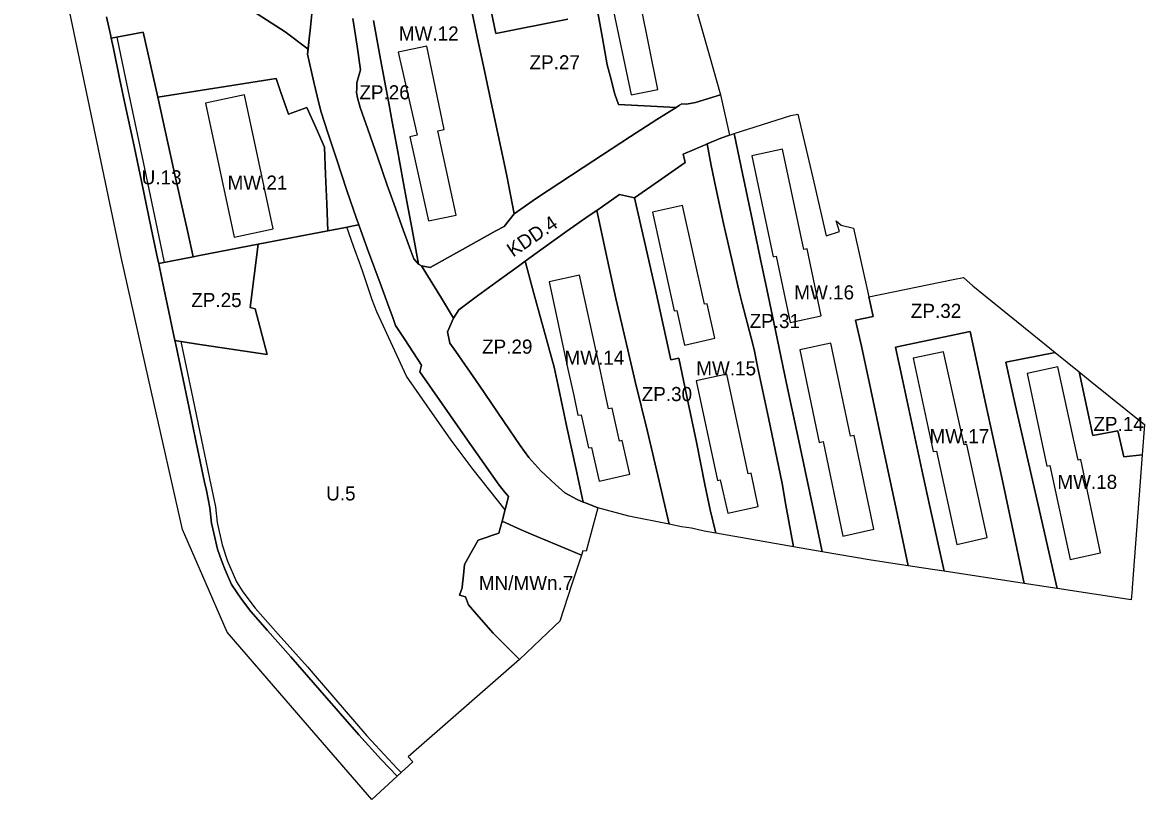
# Model space of a CAD drawing. Extents: x 7429178 to 7430831, y 5550228 to 5551611.
# Drawn here: x 7430433.7 to 7430831, y 5550228.2 to 5550503.4 of the extents above; entities that cross this region are included whole.
import ezdxf

# ---------------------------------------------------------------- set-up
doc = ezdxf.new("R2010")
doc.units = 0
for name, color, linetype in [('linie rozgraniczające', 7, 'Continuous'), ('nieprzekraczalne linie zabudowy', 7, 'Continuous'), ('obowiazujace linie zabudowy', 7, 'Continuous'), ('przeznaczenia terenów', 7, 'Continuous')]:
    doc.layers.add(name, color=color, linetype=linetype)

msp = doc.modelspace()

# ---------------------------------------------------------------- linework, layer by layer
at = {"layer": 'linie rozgraniczające'}
for points in [[(7430463.47, 5550505.4), (7430464.81, 5550499.08), (7430465.1, 5550497.73), (7430465.85, 5550494.18), (7430468.18, 5550483.03), (7430470.2, 5550473.6), (7430472.81, 5550461.18), (7430475.78, 5550447.1), (7430479.28, 5550430.48), (7430481.63, 5550419.34), (7430481.92, 5550417.95), (7430482.07, 5550417.26), (7430483.77, 5550409.2), (7430485.52, 5550400.87), (7430487.17, 5550393.01), (7430487.66, 5550390.68), (7430487.93, 5550389.35), (7430490.07, 5550379.17), (7430492.55, 5550367.33), (7430495.22, 5550354.59), (7430498.16, 5550340.56), (7430498.78, 5550337.64), (7430500.06, 5550331.51), (7430500.62, 5550325.98), (7430501.4, 5550322.46), (7430502.74, 5550316.87), (7430504.11, 5550312.77), (7430505.41, 5550309.56), (7430507.67, 5550304.34), (7430511.2, 5550299.07), (7430514.52, 5550294.71), (7430520.41, 5550288.07), (7430528.7, 5550278.73), (7430539, 5550266.95), (7430552.75, 5550251.03), (7430560.68, 5550242.37), (7430566.31, 5550236.45), (7430557.39, 5550228.16), (7430531.56, 5550258.06), (7430506.19, 5550287.45), (7430497.54, 5550307.3), (7430490.33, 5550323.77), (7430479.38, 5550372.47), (7430468.65, 5550420.22), (7430433.65, 5550586.89)], [(7430669.36, 5550518.12), (7430676.94, 5550491.5), (7430680.87, 5550477.74), (7430672.06, 5550475.04), (7430668.79, 5550474.38), (7430667.11, 5550474.51), (7430666.39, 5550474.05), (7430665.12, 5550473.25), (7430656.16, 5550473.72), (7430644.79, 5550474.31), (7430643.49, 5550477.98), (7430641.73, 5550484.5), (7430640.75, 5550488.31), (7430639.07, 5550497.75), (7430635.91, 5550515.35)], [(7430635.91, 5550515.35), (7430639.07, 5550497.75), (7430640.75, 5550488.31), (7430641.73, 5550484.5), (7430643.49, 5550477.98), (7430644.79, 5550474.31), (7430656.16, 5550473.72), (7430665.12, 5550473.25), (7430658.35, 5550468.95), (7430649.01, 5550462.97), (7430632.27, 5550451.97), (7430615.7, 5550441.07), (7430607.77, 5550435.52), (7430605.14, 5550449.03), (7430603.81, 5550455.75), (7430600.02, 5550473.41), (7430597.28, 5550486.22), (7430594.82, 5550497.67), (7430592.03, 5550510.75)], [(7430626.83, 5550504.54), (7430601.27, 5550499.45), (7430598.03, 5550515.34)], [(7430598.03, 5550515.34), (7430601.27, 5550499.45), (7430626.83, 5550504.54)], [(7430592.03, 5550510.75), (7430594.82, 5550497.67), (7430597.28, 5550486.22), (7430600.02, 5550473.41), (7430603.81, 5550455.75), (7430605.14, 5550449.03), (7430607.77, 5550435.52), (7430604.24, 5550431.08), (7430601.35, 5550429.52), (7430588.4, 5550422.32), (7430578.06, 5550416.54), (7430575.01, 5550417.17), (7430573.92, 5550417.75), (7430573.2, 5550421.63), (7430571.65, 5550430.01), (7430569.81, 5550440), (7430568.51, 5550447.02), (7430566.33, 5550458.82), (7430564.6, 5550468.19), (7430563.38, 5550474.8), (7430561.89, 5550482.84), (7430560.26, 5550491.64), (7430557.97, 5550504.04)], [(7430515.17, 5550507.41), (7430526.65, 5550500.05), (7430534.8, 5550493.86), (7430534.6, 5550492.11), (7430536.82, 5550482.25), (7430538.62, 5550474.74), (7430539.47, 5550471.53), (7430541.84, 5550464.27), (7430544.87, 5550455.02), (7430548.54, 5550443.85), (7430551.91, 5550433.97), (7430552.73, 5550431.7), (7430552.69, 5550431.69), (7430547.41, 5550430.67), (7430541.8, 5550429.58), (7430541.8, 5550429.58), (7430541.41, 5550439.12), (7430540.99, 5550449.48), (7430540.6, 5550459.21), (7430537.61, 5550465.97), (7430534.42, 5550473.22), (7430527.85, 5550470.84), (7430525.03, 5550478.9), (7430523.49, 5550483.51), (7430481.55, 5550476.95), (7430476.4, 5550499.91), (7430465.1, 5550497.73), (7430464.81, 5550499.08), (7430463.47, 5550505.4)], [(7430536.13, 5550506.36), (7430535.7, 5550501.67), (7430535.58, 5550500.57), (7430535.23, 5550497.57), (7430534.8, 5550493.86), (7430526.65, 5550500.05), (7430515.17, 5550507.41)], [(7430550.71, 5550504.77), (7430552.17, 5550494.96), (7430553.41, 5550486.58), (7430552.45, 5550483.27), (7430552.08, 5550481.98), (7430552.03, 5550479.95), (7430551.99, 5550478.5), (7430552.3, 5550476.69), (7430553.26, 5550473.29), (7430555.94, 5550465.58), (7430559.36, 5550455.73), (7430562.84, 5550445.74), (7430565.17, 5550439.27), (7430568.04, 5550431.27), (7430571.22, 5550422.45), (7430572.24, 5550419.61), (7430573.92, 5550417.75), (7430575.01, 5550417.17), (7430582.02, 5550405.75), (7430586.36, 5550398.69), (7430584.16, 5550393.82), (7430584.98, 5550389.82), (7430587.13, 5550386.83), (7430595.34, 5550374.96), (7430604.17, 5550361.99), (7430609.93, 5550353.55), (7430612.95, 5550349.25), (7430617.24, 5550344.54), (7430622.44, 5550339.68), (7430625.72, 5550336.82), (7430630.08, 5550334.37), (7430632.26, 5550333.51), (7430633.1, 5550333.18), (7430637.45, 5550331.47), (7430633.28, 5550316.09), (7430632.08, 5550316.29), (7430631.58, 5550314.75), (7430627.17, 5550316.57), (7430614.42, 5550321.85), (7430610.22, 5550323.65), (7430603.51, 5550326.71), (7430605.78, 5550335.49), (7430604.31, 5550337.16), (7430602.43, 5550339.52), (7430597.18, 5550347.02), (7430590.49, 5550356.6), (7430582.3, 5550368.33), (7430574.42, 5550379.6), (7430574.96, 5550381.99), (7430569.02, 5550391.12), (7430565.8, 5550396.07), (7430564.76, 5550398.9), (7430563.53, 5550402.24), (7430560.66, 5550410.03), (7430555.85, 5550423.12), (7430552.73, 5550431.7), (7430551.91, 5550433.97), (7430548.54, 5550443.85), (7430544.87, 5550455.02), (7430541.84, 5550464.27), (7430539.47, 5550471.53), (7430538.62, 5550474.74), (7430536.82, 5550482.25), (7430534.6, 5550492.11), (7430535.23, 5550497.57), (7430535.7, 5550501.67), (7430536.13, 5550506.36)], [(7430557.97, 5550504.04), (7430560.26, 5550491.64), (7430561.89, 5550482.84), (7430563.38, 5550474.8), (7430564.6, 5550468.19), (7430566.33, 5550458.82), (7430568.51, 5550447.02), (7430569.81, 5550440), (7430571.65, 5550430.01), (7430573.2, 5550421.63), (7430573.92, 5550417.75), (7430572.24, 5550419.61), (7430571.22, 5550422.45), (7430568.04, 5550431.27), (7430565.17, 5550439.27), (7430562.84, 5550445.74), (7430559.36, 5550455.73), (7430555.94, 5550465.58), (7430553.26, 5550473.29), (7430552.3, 5550476.69), (7430551.99, 5550478.5), (7430552.03, 5550479.95), (7430552.08, 5550481.98), (7430552.45, 5550483.27), (7430553.41, 5550486.58), (7430552.17, 5550494.96), (7430550.71, 5550504.77)]]:
    msp.add_lwpolyline(points, dxfattribs=at)
for points in [[(7430481.55, 5550476.95), (7430481.55, 5550476.95), (7430487.9, 5550448.31), (7430492.05, 5550429.56), (7430494.1, 5550420.32), (7430481.92, 5550417.95), (7430481.92, 5550417.95), (7430481.63, 5550419.34), (7430479.28, 5550430.48), (7430475.78, 5550447.1), (7430472.81, 5550461.18), (7430470.2, 5550473.6), (7430468.18, 5550483.03), (7430465.85, 5550494.18), (7430465.1, 5550497.73), (7430476.4, 5550499.91)], [(7430534.42, 5550473.22), (7430537.61, 5550465.97), (7430540.6, 5550459.21), (7430540.99, 5550449.48), (7430541.41, 5550439.12), (7430541.8, 5550429.58), (7430541.8, 5550429.58), (7430534.35, 5550428.13), (7430517.1, 5550424.79), (7430496.39, 5550420.77), (7430494.1, 5550420.32), (7430492.05, 5550429.56), (7430487.9, 5550448.31), (7430481.55, 5550476.95), (7430523.49, 5550483.51), (7430525.03, 5550478.9), (7430527.85, 5550470.84)], [(7430680.87, 5550477.74), (7430684, 5550463.45), (7430680.93, 5550462.41), (7430676.1, 5550460.36), (7430675.41, 5550460.07), (7430667.68, 5550456.73), (7430668.34, 5550453.76), (7430658.88, 5550447.15), (7430650.41, 5550441.24), (7430645.09, 5550442.42), (7430637.06, 5550436.81), (7430634.37, 5550434.93), (7430626.47, 5550429.4), (7430618.11, 5550423.39), (7430611.72, 5550418.79), (7430609.3, 5550417.05), (7430601.31, 5550411.24), (7430594.86, 5550406.5), (7430588.18, 5550401.59), (7430586.36, 5550398.69), (7430582.02, 5550405.75), (7430575.01, 5550417.17), (7430578.06, 5550416.54), (7430588.4, 5550422.32), (7430601.35, 5550429.52), (7430604.24, 5550431.08), (7430607.77, 5550435.52), (7430615.7, 5550441.07), (7430632.27, 5550451.97), (7430649.01, 5550462.97), (7430658.35, 5550468.95), (7430665.12, 5550473.25), (7430666.39, 5550474.05), (7430667.11, 5550474.51), (7430668.79, 5550474.38), (7430672.06, 5550475.04)], [(7430733.35, 5550406.14), (7430734.98, 5550399.25), (7430728.66, 5550397.97), (7430730.78, 5550388.71), (7430733.57, 5550375.55), (7430738.46, 5550352.61), (7430742.55, 5550333.4), (7430747.34, 5550310.92), (7430734.19, 5550312.93), (7430716.82, 5550315.93), (7430715.39, 5550322.73), (7430713.74, 5550330.6), (7430711.61, 5550340.7), (7430708.23, 5550356.79), (7430704.28, 5550375.55), (7430700.34, 5550394.29), (7430697.27, 5550408.89), (7430694.92, 5550420.05), (7430692.18, 5550433.08), (7430688.17, 5550452.12), (7430685.68, 5550463.98), (7430705.8, 5550470.37), (7430708.25, 5550470.87), (7430713.5, 5550448.27), (7430718.25, 5550427.81), (7430723.03, 5550429.28), (7430721.86, 5550433.07), (7430723.57, 5550431.62), (7430728, 5550430.52), (7430730.68, 5550418.35)], [(7430715.39, 5550322.73), (7430716.82, 5550315.93), (7430706.65, 5550317.69), (7430704.05, 5550332.38), (7430702.65, 5550340.05), (7430697.81, 5550363.32), (7430693.99, 5550381.56), (7430692.78, 5550387.5), (7430691.7, 5550391.7), (7430688.58, 5550403.85), (7430687.36, 5550408.58), (7430685.1, 5550418.31), (7430681.89, 5550432.12), (7430679.16, 5550444.78), (7430677.61, 5550452.67), (7430676.1, 5550460.36), (7430680.93, 5550462.41), (7430684, 5550463.45), (7430685.68, 5550463.98), (7430688.17, 5550452.12), (7430692.18, 5550433.08), (7430694.92, 5550420.05), (7430697.27, 5550408.89), (7430700.34, 5550394.29), (7430704.28, 5550375.55), (7430708.23, 5550356.79), (7430711.61, 5550340.7), (7430713.74, 5550330.6)], [(7430692.78, 5550387.5), (7430693.99, 5550381.56), (7430697.81, 5550363.32), (7430702.65, 5550340.05), (7430704.05, 5550332.38), (7430706.65, 5550317.69), (7430679.15, 5550322.45), (7430677.25, 5550330.79), (7430675.36, 5550339.75), (7430672.3, 5550354.71), (7430669.4, 5550368.69), (7430666.1, 5550384.49), (7430663.23, 5550383.82), (7430657.83, 5550408.67), (7430653.92, 5550425.83), (7430650.41, 5550441.24), (7430658.88, 5550447.15), (7430668.34, 5550453.76), (7430667.68, 5550456.73), (7430675.41, 5550460.07), (7430676.1, 5550460.36), (7430677.61, 5550452.67), (7430679.16, 5550444.78), (7430681.89, 5550432.12), (7430685.1, 5550418.31), (7430687.36, 5550408.58), (7430688.58, 5550403.85), (7430691.7, 5550391.7)], [(7430650.41, 5550441.24), (7430653.92, 5550425.83), (7430657.83, 5550408.67), (7430663.23, 5550383.82), (7430666.1, 5550384.49), (7430669.4, 5550368.69), (7430672.3, 5550354.71), (7430675.36, 5550339.75), (7430677.25, 5550330.79), (7430679.15, 5550322.45), (7430675.03, 5550323.16), (7430670.62, 5550324.29), (7430667.07, 5550324.77), (7430662.63, 5550325.67), (7430659.09, 5550340.87), (7430655, 5550358.46), (7430650.62, 5550376.16), (7430648.01, 5550387.41), (7430643.82, 5550405.64), (7430640.81, 5550419.13), (7430637.06, 5550436.81), (7430645.09, 5550442.42)], [(7430659.09, 5550340.87), (7430662.63, 5550325.67), (7430648.44, 5550328.54), (7430637.45, 5550331.47), (7430633.1, 5550333.18), (7430632.26, 5550333.51), (7430631.54, 5550336.8), (7430629.73, 5550345.09), (7430626.45, 5550360.05), (7430623.38, 5550374.62), (7430621.99, 5550381.23), (7430620.08, 5550388.09), (7430614.78, 5550407.32), (7430611.72, 5550418.79), (7430618.11, 5550423.39), (7430626.47, 5550429.4), (7430634.37, 5550434.93), (7430637.06, 5550436.81), (7430640.81, 5550419.13), (7430643.82, 5550405.64), (7430648.01, 5550387.41), (7430650.62, 5550376.16), (7430655, 5550358.46)], [(7430569.02, 5550391.12), (7430574.96, 5550381.99), (7430574.42, 5550379.6), (7430582.3, 5550368.33), (7430590.49, 5550356.6), (7430597.18, 5550347.02), (7430602.43, 5550339.52), (7430604.31, 5550337.16), (7430605.78, 5550335.49), (7430603.51, 5550326.71), (7430602.41, 5550322.45), (7430595, 5550320.05), (7430592.53, 5550315.61), (7430590.15, 5550311.34), (7430589.69, 5550306.44), (7430589.53, 5550304.7), (7430589.38, 5550303.1), (7430588.39, 5550300.54), (7430590.56, 5550299.9), (7430591.63, 5550297.09), (7430594.43, 5550293.86), (7430600.34, 5550287.04), (7430604.94, 5550282.52), (7430609.72, 5550277.81), (7430606.82, 5550275.27), (7430570.2, 5550243.23), (7430571.89, 5550241.54), (7430566.31, 5550236.45), (7430560.68, 5550242.37), (7430552.75, 5550251.03), (7430539, 5550266.95), (7430528.7, 5550278.73), (7430520.41, 5550288.07), (7430514.52, 5550294.71), (7430511.2, 5550299.07), (7430507.67, 5550304.34), (7430505.41, 5550309.56), (7430504.11, 5550312.77), (7430502.74, 5550316.87), (7430501.4, 5550322.46), (7430500.62, 5550325.98), (7430500.06, 5550331.51), (7430498.78, 5550337.64), (7430498.16, 5550340.56), (7430495.22, 5550354.59), (7430492.55, 5550367.33), (7430490.07, 5550379.17), (7430487.93, 5550389.35), (7430487.66, 5550390.68), (7430494.94, 5550389.58), (7430520.36, 5550385.77), (7430516.08, 5550401.95), (7430514.24, 5550402.35), (7430517.1, 5550424.79), (7430534.35, 5550428.13), (7430547.41, 5550430.67), (7430552.69, 5550431.69), (7430552.73, 5550431.7), (7430552.73, 5550431.7), (7430555.85, 5550423.12), (7430560.66, 5550410.03), (7430563.53, 5550402.24), (7430564.76, 5550398.9), (7430565.8, 5550396.07)], [(7430516.08, 5550401.95), (7430520.36, 5550385.77), (7430494.94, 5550389.58), (7430487.66, 5550390.68), (7430487.17, 5550393.01), (7430485.52, 5550400.87), (7430483.77, 5550409.2), (7430482.07, 5550417.26), (7430481.92, 5550417.95), (7430481.92, 5550417.95), (7430494.1, 5550420.32), (7430496.39, 5550420.77), (7430517.1, 5550424.79), (7430514.24, 5550402.35)], [(7430631.54, 5550336.8), (7430632.26, 5550333.51), (7430630.08, 5550334.37), (7430625.72, 5550336.82), (7430622.44, 5550339.68), (7430617.24, 5550344.54), (7430612.95, 5550349.25), (7430609.93, 5550353.55), (7430604.17, 5550361.99), (7430595.34, 5550374.96), (7430587.13, 5550386.83), (7430584.98, 5550389.82), (7430584.16, 5550393.82), (7430586.36, 5550398.69), (7430588.18, 5550401.59), (7430594.86, 5550406.5), (7430601.31, 5550411.24), (7430609.3, 5550417.05), (7430611.72, 5550418.79), (7430614.78, 5550407.32), (7430620.08, 5550388.09), (7430621.99, 5550381.23), (7430623.38, 5550374.62), (7430626.45, 5550360.05), (7430629.73, 5550345.09)], [(7430799.36, 5550386.53), (7430781.86, 5550383), (7430785.26, 5550368.07), (7430793.24, 5550333.03), (7430800.12, 5550302.85), (7430788.38, 5550304.65), (7430785.34, 5550319.3), (7430780.56, 5550341.58), (7430774.78, 5550368.09), (7430769.23, 5550393.89), (7430742.88, 5550388.36), (7430745.47, 5550376.38), (7430752.56, 5550343.23), (7430754.94, 5550331.92), (7430760.06, 5550308.98), (7430755.89, 5550309.62), (7430747.34, 5550310.92), (7430742.55, 5550333.4), (7430738.46, 5550352.61), (7430733.57, 5550375.55), (7430730.78, 5550388.71), (7430728.66, 5550397.97), (7430734.98, 5550399.25), (7430733.35, 5550406.14), (7430763.28, 5550412.28), (7430766.87, 5550413.01), (7430770.26, 5550410.06), (7430774.56, 5550406.59), (7430793.72, 5550391.1)], [(7430788.38, 5550304.65), (7430760.06, 5550308.98), (7430754.94, 5550331.92), (7430752.56, 5550343.23), (7430745.47, 5550376.38), (7430742.88, 5550388.36), (7430769.23, 5550393.89), (7430774.78, 5550368.09), (7430780.56, 5550341.58), (7430785.34, 5550319.3)], [(7430807.89, 5550379.63), (7430812.77, 5550357.09), (7430821.61, 5550358.79), (7430823.65, 5550349.55), (7430830.22, 5550350.19), (7430826.66, 5550303.14), (7430826.6, 5550302.71), (7430826.34, 5550298.84), (7430800.12, 5550302.85), (7430793.24, 5550333.03), (7430785.26, 5550368.07), (7430781.86, 5550383), (7430799.36, 5550386.53)], [(7430830.22, 5550350.19), (7430823.65, 5550349.55), (7430821.61, 5550358.79), (7430812.77, 5550357.09), (7430807.89, 5550379.63), (7430811.81, 5550376.46), (7430831.03, 5550360.92)], [(7430609.72, 5550277.81), (7430604.94, 5550282.52), (7430600.34, 5550287.04), (7430594.43, 5550293.86), (7430591.63, 5550297.09), (7430590.56, 5550299.9), (7430588.39, 5550300.54), (7430589.38, 5550303.1), (7430589.53, 5550304.7), (7430589.69, 5550306.44), (7430590.15, 5550311.34), (7430592.53, 5550315.61), (7430595, 5550320.05), (7430602.41, 5550322.45), (7430603.51, 5550326.71), (7430610.22, 5550323.65), (7430614.42, 5550321.85), (7430627.17, 5550316.57), (7430631.58, 5550314.75), (7430628.23, 5550304.39), (7430623.99, 5550291.3), (7430622.1, 5550289.51)]]:
    msp.add_lwpolyline(points, close=True, dxfattribs=at)
at = {"layer": 'nieprzekraczalne linie zabudowy'}
for points in [[(7430467.06, 5550498.14), (7430470.14, 5550483.44), (7430471.82, 5550475.61), (7430476.39, 5550453.92), (7430482.45, 5550425.15), (7430483.88, 5550418.36)], [(7430604.57, 5550330.81), (7430593.27, 5550345.05), (7430585.46, 5550355.37), (7430577.03, 5550367.53), (7430569.62, 5550378.1), (7430560.03, 5550399.12), (7430559.1, 5550400.87), (7430557.48, 5550405.16), (7430555.73, 5550410.42), (7430554.56, 5550413.95), (7430554.05, 5550415.35), (7430552.49, 5550419.63), (7430551.85, 5550421.48), (7430550.92, 5550424.14), (7430549.4, 5550428.53), (7430549.05, 5550429.51), (7430548.69, 5550430.51), (7430548.56, 5550430.88)], [(7430489.77, 5550390.36), (7430493.53, 5550372.41), (7430497.56, 5550353.21), (7430499.95, 5550341.8), (7430502.04, 5550331.82), (7430502.6, 5550326.3), (7430504.35, 5550318.37), (7430506.28, 5550312.58), (7430509.44, 5550305.28), (7430511.72, 5550301.68), (7430516.07, 5550295.98), (7430524.25, 5550286.76), (7430534.58, 5550275.12), (7430536.56, 5550272.84), (7430555.62, 5550250.76), (7430566.34, 5550239.21), (7430567.7, 5550237.88)], [(7430631.58, 5550314.75), (7430627.6, 5550316.4), (7430619.77, 5550319.64), (7430613.99, 5550322.03), (7430611.52, 5550323.05), (7430608.4, 5550324.48), (7430603.51, 5550326.71)]]:
    msp.add_lwpolyline(points, dxfattribs=at)
at = {"layer": 'obowiazujace linie zabudowy'}
for points in [[(7430648.28, 5550539.64), (7430638.89, 5550537.58), (7430644.92, 5550507.82), (7430642.96, 5550507.39), (7430649.21, 5550477.72), (7430658.7, 5550479.62), (7430652.68, 5550509.5), (7430654.69, 5550509.93), (7430648.28, 5550539.64)], [(7430587.21, 5550435.15), (7430580.7, 5550465.01), (7430582.98, 5550465.49), (7430576.86, 5550494.94), (7430566.72, 5550492.83), (7430573.46, 5550463.49), (7430570.85, 5550462.83), (7430577.42, 5550433.08), (7430587.21, 5550435.15)], [(7430498.5, 5550474.81), (7430508.62, 5550427.26), (7430522.41, 5550430.22), (7430512.26, 5550477.75), (7430498.5, 5550474.81)], [(7430702.81, 5550458.42), (7430692, 5550456.08), (7430699.51, 5550420.37), (7430700.55, 5550420.6), (7430705.51, 5550397.05), (7430716.51, 5550399.46), (7430711.49, 5550423.19), (7430710.37, 5550422.93), (7430702.81, 5550458.42)], [(7430667.42, 5550438.56), (7430656.73, 5550436.15), (7430664.44, 5550401.21), (7430665.35, 5550401.37), (7430668.13, 5550389.03), (7430678.85, 5550391.53), (7430676.09, 5550403.71), (7430675.2, 5550403.57), (7430667.42, 5550438.56)], [(7430648.69, 5550343.43), (7430646.08, 5550355.26), (7430645.12, 5550355.1), (7430642.54, 5550366.81), (7430641.22, 5550366.55), (7430639.67, 5550373.7), (7430637.61, 5550383.18), (7430630.95, 5550413.82), (7430620.13, 5550411.5), (7430626.83, 5550380.62), (7430628.87, 5550371.24), (7430630.35, 5550364.23), (7430631.46, 5550364.42), (7430634.14, 5550352.66), (7430635.21, 5550352.87), (7430637.85, 5550340.96), (7430648.69, 5550343.43)], [(7430735.16, 5550323.94), (7430728.17, 5550357.07), (7430726.86, 5550356.83), (7430719.96, 5550389.72), (7430708.91, 5550387.46), (7430715.81, 5550354.57), (7430717.21, 5550354.92), (7430724.23, 5550321.46), (7430735.16, 5550323.94)], [(7430775.26, 5550320.92), (7430768.05, 5550353.86), (7430767.12, 5550353.72), (7430759.79, 5550386.73), (7430749.03, 5550384.44), (7430756.22, 5550351.38), (7430757.31, 5550351.59), (7430764.53, 5550318.53), (7430775.26, 5550320.92)], [(7430815.47, 5550315.51), (7430808.5, 5550348.59), (7430807.48, 5550348.39), (7430800.37, 5550381.44), (7430789.44, 5550379.08), (7430796.47, 5550346.17), (7430797.53, 5550346.43), (7430804.71, 5550313.17), (7430815.47, 5550315.51)], [(7430683.05, 5550378.76), (7430672.2, 5550376.48), (7430679.8, 5550341.18), (7430680.76, 5550341.34), (7430683.46, 5550329.54), (7430694.2, 5550331.9), (7430691.7, 5550343.75), (7430690.63, 5550343.52), (7430683.05, 5550378.76)]]:
    msp.add_lwpolyline(points, dxfattribs=at)

# ---------------------------------------------------------------- texts
at = {"layer": 'przeznaczenia terenów'}
for s, p in [('MW.12', (7430566.96, 5550496.95)), ('ZP.27', (7430613.23, 5550486.74)), ('ZP.26', (7430552.97, 5550476.11)), ('U.13', (7430475.88, 5550446)), ('MW.21', (7430506.3, 5550444.13)), ('MW.16', (7430706.98, 5550405.27)), ('ZP.25', (7430493.44, 5550402.55)), ('ZP.32', (7430748.28, 5550398.71)), ('ZP.31', (7430691.17, 5550395.13)), ('ZP.29', (7430596.42, 5550386.05)), ('MW.14', (7430625.6, 5550382.13)), ('MW.15', (7430672.27, 5550378.37)), ('ZP.30', (7430652.95, 5550369.26)), ('ZP.14', (7430812.91, 5550358.66)), ('MW.17', (7430754.87, 5550354.36)), ('MW.18', (7430800.15, 5550338.15)), ('U.5', (7430541.21, 5550334.08)), ('MN/MWn.7', (7430595.29, 5550302.38))]:
    msp.add_text(s, height=5, dxfattribs=at).set_placement(p)
msp.add_text('KDD.4', height=5, rotation=34.0601, dxfattribs=at).set_placement((7430607.37, 5550420.07))

doc.saveas('drawing.dxf')
